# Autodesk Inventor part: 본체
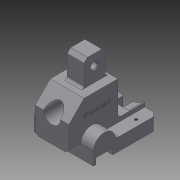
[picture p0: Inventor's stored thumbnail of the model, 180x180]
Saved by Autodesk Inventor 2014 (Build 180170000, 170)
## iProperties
Created: 2016-11
Part Number: 본체
Material: 일반
Document SubType Name: Modeling
Designer: USER
Density: 1 g/cm^3
Appearance: 기본값
Author: USER
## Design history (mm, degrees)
sketch "스케치1"
  geometry: L1 (-13, 0)-(-13, -15); L2 (63, -15)-(63, 0); L3 (63, 0)-(13, 0); L4 (10, -15)-(10, -8); L5 (10, -8)-(-10, -8); L6 (-10, -8)-(-10, -15); L7 (-13, -15)-(-10, -15); L8 (10, -15)-(63, -15); A1 r 13 centre (0, 0) between (13, 0) and (-13, 0); 2 further points
  constraints: 16 end point, 4 parallel, 2 perpendicular, 2 point on circle, 1 centre point, 1 coincident, 1 horizontal alignment, 1 midpoint, 1 tangent, 1 vertical, 1 vertical alignment
  dimensions: "d0" = 26 diameter of A1; "d2" = 63 distance from line of L2 point (0, 0); "d3" = 15 distance between parallel lines of L8 L3; "d7" = 20 distance of L4.end L5.end; "d8" = 3 distance of L1.end L6.end; "d9" = 7 distance between parallel lines of L5 L7; "d10" = 8 distance between parallel lines of L3 L5
extrude "돌출1" new body sketch "스케치1" stored distance "d11" = 70; taper "d12" = 0 deg
sketch "스케치2"
  geometry: L1 (13, 0)-(63, 0) reference; L2 (63, 0)-(63, -15) reference; L3 (63, -15)-(10, -15) reference; L4 (10, -15)-(10, -8) reference; L5 (10, -8)-(-10, -8) reference; L6 (-10, -8)-(-10, -15) reference; L7 (-10, -15)-(-13, -15) reference; L8 (-13, -15)-(-13, 0) reference; L9 (-13, -3)-(-27, -3); L10 (-27, -3)-(-27, 27); L11 (-27, 27)-(-9, 45); L12 (-9, 45)-(31, 45); L13 (31, 45)-(31, 5); L14 (31, 5)-(63, 5); L15 (63, 5)-(63, 0); A1 r 13 centre (0, 0) between (13, 0) and (-13, 0) reference; 1 further point
  constraints: 14 end point, 4 perpendicular, 1 collinear, 1 parallel, 1 point on line
  dimensions: "d13" = 58 distance between parallel lines of L13 L10; "d14" = 32 distance between parallel lines of L2 L13; "d15" = 18 horizontal distance of L11.end L10.end; "d16" = 45 deg angle of L12 L11; "d17" = 48 distance between parallel lines of L9 L12; "d18" = 30 distance of L9.end L10.end (derived); "d19" = 90 distance between parallel lines of L2 L10 (derived); "d20" = 40 distance of L11.end L12.end (derived); "d21" = 60 distance between parallel lines of L3 L12; "d26" = 20 distance between parallel lines of L3 L14
extrude "돌출2" join sketch "스케치2" stored distance "d22" = 40; taper "d23" = 0 deg
node "작업 평면2"
sketch "스케치3"
  geometry: L1 (55, 60)-(15, 60) reference; L2 (15, 20)-(15, 60) reference; L3 (55, 60)-(55, 20) reference; L4 (0, 0)-(70, 0) reference; L5 (0, 15)-(70, 15) reference; L6 (15, 42)-(55, 42); L7 (55, 20)-(15, 20) reference; L8 (29, 13.627)-(29, 0); L9 (41, 13.627)-(41, 0); L10 (30.246, 0)-(41, 0); L11 (16.106, 20)-(53.894, 20); A1 r 29 centre (35, 42) between (16.106, 20) and (53.894, 20); 5 further points
  constraints: 10 end point, 7 point on line, 4 point on circle, 3 perpendicular, 2 collinear, 2 midpoint, 1 centre point, 1 coincident, 1 vertical alignment
  dimensions: "d24" = 42 distance between parallel lines of L4 L6; "d25" = 58 diameter of A1; "d27" = 6 distance from line of L8 point (35, 15); "d28" = 6 distance from line of L9 point (35, 15)
extrude "돌출3" cut sketch "스케치3" distance "d29" = 18; taper "d30" = 0 deg
sketch "스케치4"
  geometry: L1 (-13, -3)-(-13, 0) reference; L2 (-13, -3)-(-27, -3) reference; L3 (-27, -3)-(-27, 27) reference; L4 (-27, 27)-(-9, 45) reference; L5 (-9, 45)-(31, 45) reference; L6 (31, 45)-(31, 5) reference; L7 (31, 5)-(63, 5) reference; L8 (63, 5)-(63, 0) reference; L9 (13, 0)-(63, 0) reference; L10 (1, 45)-(1, 75); L11 (1, 75)-(26, 75); L12 (26, 75)-(26, 45); L13 (63, -15)-(10, -15) reference; A1 r 13 centre (0, 0) between (13, 0) and (-13, 0) reference; 1 further point
  constraints: 6 end point, 3 perpendicular, 2 point on line
  dimensions: "d31" = 5 distance between parallel lines of L6 L12; "d32" = 25 distance of L10.end L11.end; "d33" = 90 distance between parallel lines of L13 L11
extrude "돌출4" join sketch "스케치4" stored distance "d34" = 20; taper "d35" = 0 deg
chamfer "모따기1" distance "d36" = 4; stored, may be unused: second distance "d37" = 2, angle "d38" = 45 deg
sketch "스케치5"
  geometry: L1 (0, 0)-(40, 0) reference; L2 (38.894, 40)-(1.106, 40) reference; 4 further points
  constraints: 1 midpoint, 1 vertical alignment
  dimensions: "d85" = 30 vertical distance of point (40, 48) point (20, 18)
hole "구멍1" sketch "스케치5" at (20, 18) diameter "d39" = 20; stored, may be unused: countersink angle "d43" = 90 deg, drill point angle "d45" = 118 deg; dims "d40" = 6, "d41" = 29, "d42" = 7, "d44" = 8
sketch "스케치7"
  geometry: L1 (75, 5)-(75, 22) reference; L2 (-15, 10)-(-15, 63) reference; L3 (27, -27)-(27, -27) reference; L4 (27, -27)-(27, -27) reference; L5 (37, 24)-(17, 24) reference; 3 further points
  constraints: 1 horizontal alignment, 1 midpoint
  dimensions: "d46" = 77 distance from line of L2 point (62, 13.5); "d86" = 35 horizontal distance of L3.start point (62, 13.5) (derived)
hole "구멍2" sketch "스케치7" at (62, 13.5) diameter "d47" = 8; stored, may be unused: countersink angle "d51" = 90 deg, drill point angle "d53" = 118 deg; dims "d48" = 6, "d49" = 29, "d50" = 7, "d52" = 8
sketch "스케치8"
  geometry: L1 (15, 50)-(0, 50) reference; 2 further points
  dimensions: "d54" = 18 distance from line of L1 point (7.5, 32); "d55" = 27.5 horizontal distance of point (35, -13) point (7.5, 32)
hole "구멍3" sketch "스케치8" at (7.5, 32) diameter "d56" = 3.459; stored, may be unused: countersink angle "d60" = 90 deg, drill point angle "d62" = 0 deg; dims "d57" = 30, "d58" = 29, "d59" = 7, "d61" = 30
sketch "스케치9"
  geometry: L1 (-5, 31)-(-45, 31) reference; L2 (-45, 31)-(-45, -9) reference; 1 further point
  constraints: 1 other
  dimensions: "d63" = 18 distance from line of L2 point (-27, 6); "d64" = 25 distance from line of L1 point (-27, 6)
feature "엠보싱1" sketch "스케치9" dims "d0" = 26, "d2" = 63, "d3" = 15, "d7" = 20, "d8" = 3, "d9" = 7, "d10" = 8, "d65" = 0.5, "d66" = 0
chamfer "모따기2" distance "d67" = 1; stored, may be unused: second distance "d68" = 2, angle "d69" = 45 deg
chamfer "모따기3" distance "d70" = 1; stored, may be unused: second distance "d71" = 2, angle "d72" = 45 deg
chamfer "모따기4" distance "d73" = 1; stored, may be unused: second distance "d74" = 2, angle "d75" = 45 deg
fillet "모깎기1" dims "d76" = 3
fillet "모깎기2" dims "d77" = 5
fillet "모깎기3" dims "d78" = 3
chamfer "모따기5" distance "d79" = 4; stored, may be unused: second distance "d80" = 2, angle "d81" = 45 deg
chamfer "모따기6" distance "d82" = 4; stored, may be unused: second distance "d83" = 2, angle "d84" = 45 deg
chamfer "모따기7" distance "d87" = 5; stored, may be unused: second distance "d88" = 2, angle "d89" = 45 deg
node "솔리드1"
mirror "대칭1"
node "투영된 루프1"
node "투영된 루프2"
node "투영된 루프3"
node "작업 평면3"
node "투영된 루프6"
other parameters: "d1" = 15
